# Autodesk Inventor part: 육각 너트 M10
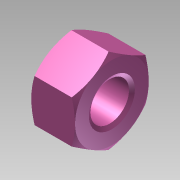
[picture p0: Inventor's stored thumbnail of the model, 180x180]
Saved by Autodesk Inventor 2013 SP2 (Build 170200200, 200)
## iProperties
Created: 2025-04
Part Number: 육각 너트 M10
Material: Generic
Document SubType Name: Modeling
Designer: i
Density: 1 g/cm^3
Author: i
변환 표준: STEP AP214IS
전처리기: Build: 200, Release: 2013 SP2 Update 6 - Date: Thu 07/17/2014
전송 단위: 밀리미터
불확실성: 0.01
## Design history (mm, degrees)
node "육각 너트 M101"
body "Solid1"
node "기준1"
